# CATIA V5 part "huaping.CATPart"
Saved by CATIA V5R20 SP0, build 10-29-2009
Part number: Part2
Material "Multicoloured Flag"
Material "DS Light Blue": density 7860 kg/m3, Young's modulus 2e+11 Pa, Poisson ratio 0.266
Bounding box of the stored display mesh (mm): x -186.271 to 34.998, y -70.037 to 61.876, z 0 to 132.474
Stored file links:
  C:\Users\ysz\Desktop\新建文件夹 (2)\huaping.CATPart
  D:\CATIAR20\win_b64\startup\materials\Catalog.CATMaterial
  D:\CATIAR20\win_b64\startup\materials\blue_env_512x512.jpg
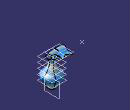
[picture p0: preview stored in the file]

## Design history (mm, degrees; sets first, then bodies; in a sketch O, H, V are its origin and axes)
Set1
  Plane1: type Offset, RefPlane xy-plane, Offset 20
  Plane2: type Offset, RefPlane Plane1, Offset 20
  Plane3: type Offset, RefPlane Plane2, Offset 20
  Plane4: type Offset, RefPlane Plane3, Offset 20
  Sketch1 on Plane4, origin (0, 0, 80), H (1, 0, 0), V (0, 1, 0)
    circle A1 centre (0, 0) radius 10
    radius A1 = 10
  Sketch2 on Plane3, origin (0, 0, 60), H (1, 0, 0), V (0, 1, 0)
    circle A1 centre (0, 0) radius 17.5
    radius A1 = 17.5
  Sketch3 on Plane2, origin (0, 0, 40), H (1, 0, 0), V (0, 1, 0)
    circle A1 centre (0, 0) radius 35
    radius A1 = 35
  Sketch4 on Plane1, origin (0, 0, 20), H (1, 0, 0), V (0, 1, 0)
    circle A1 centre (0, 0) radius 25
    radius A1 = 25
  Sketch5 on xy-plane, origin (0, 0, 0), H (1, 0, 0), V (0, 1, 0)
    circle A1 centre (0, 0) radius 15
    radius A1 = 15
  Plane5: type Offset, RefPlane Plane4, Offset 20
  Sketch6 on Plane5, origin (0, 0, 100), H (1, 0, 0), V (0, 1, 0)
    circle A1 centre (0, 0) radius 17.5
    radius A1 = 17.5
Body1 (main body), material "Multicoloured Flag"
  Loft1: solid, Sections (Sketch6; Sketch1; Sketch2; Sketch3; Sketch4; Sketch5)
  Shell1: IntOffset 1, Face face of Loft1, ExtOffset 0
  Point1: type OnPlane, Support Plane1, H -186.271, V -70.037, Direction (1, 0, 0)
  Sketch7 on yz-plane, origin (0, 0, 0), H (0, 1, 0), V (0, 0, 1)
    line L1 (10, 0) -> (10, 20)
    arc A1 centre (-45, 35) radius 57.0088 from (10, 20) to (0, 70) ccw
    point P4 (0, 70)
    spline S1 through (0, 70) (0, 110) (10, 130) (30, 130)
    point P5 (0, 70)
    vertical: L1 V
    coincidence: A1 O, P5 P4
  Pad1: profile Sketch7, direction (1, 0, 0), length 2, thin wall 1
  Plane6: type OffsetPt, RefPlane Plane5, RefPoint vertex [end face of Pad1 | face of Pad1 | face of Pad1]
  Fillet1: radius 0.3, on edge [face of Shell1 | face of Loft1]; edge [face of Loft1 | face of Loft1]
  Sketch8 on Plane6, origin (0, 0, 129.0758), H (1, 0, 0), V (0, 1, 0)
    spline S1 through (0, 50) (20, 60) (20, 30) (30, 20) (0, 10) (-30, 20) (-20, 40) (-20, 60) (0, 50)
    point P1 (0, 10)
    point P2 (0, 50)
    point P3 (0, 50)
    coincidence: P1 V, P2 P3
  Pad2: profile Sketch8, direction (0, 0, 1), length 2
Body2, material "DS Light Blue"
  Sketch9 on yz-plane, origin (0, 0, 0), H (0, 1, 0), V (0, 0, 1)
    line L1 (-28.4237, 29.5494) -> (-15.2826, 2.1435)
    line L2 (-15.2826, 2.1435) -> (-2.9379, 2.1435)
    line L3 (-2.9379, 2.1435) -> (-2.9379, 29.5494)
    line L4 (-2.9379, 29.5494) -> (-28.4237, 29.5494)
    horizontal: L2 H, L4 H
    vertical: L3 V
  Shaft1: profile Sketch9, axis Sketch9.V, angle 360, thin wall 1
